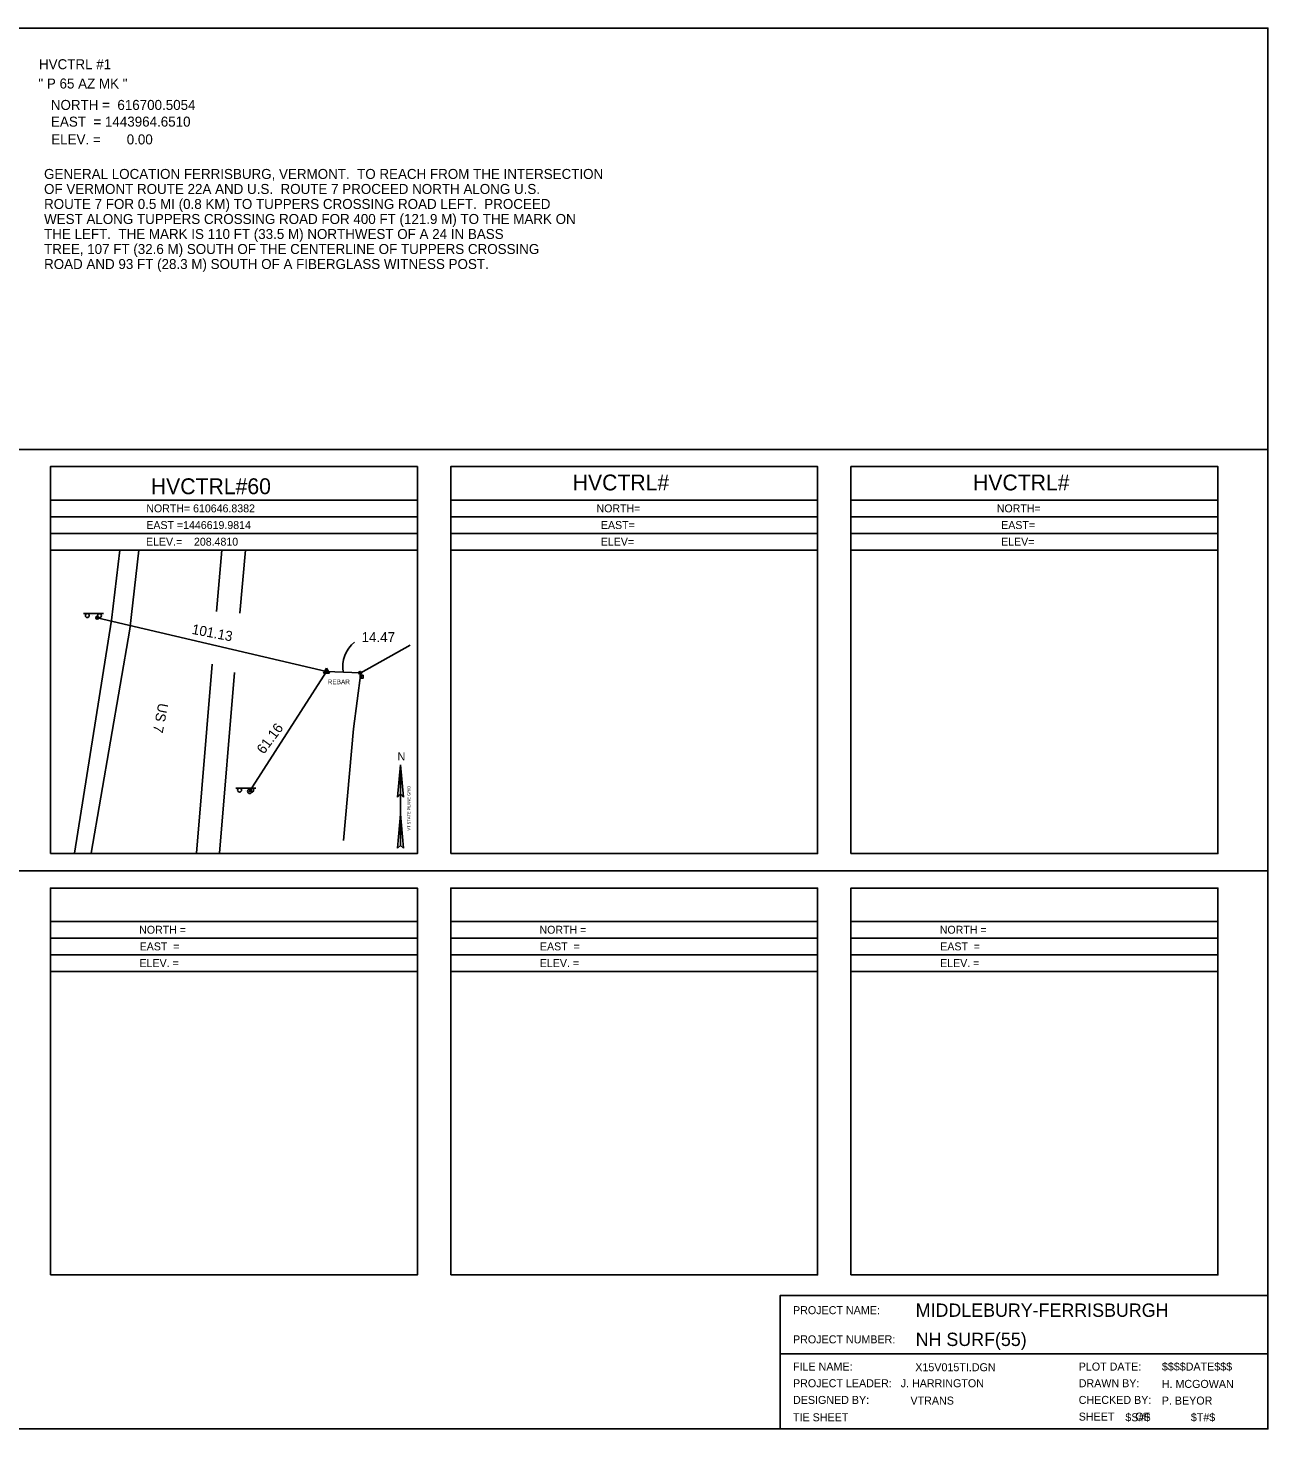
# Model space of a CAD drawing. Extents: x 1514039 to 1514679, y 870735 to 871155.
# Drawn here: x 1514306.9 to 1514678.6, y 870735.2 to 871155.2 of the extents above; entities that cross this region are included whole.
import ezdxf

# ---------------------------------------------------------------- set-up
doc = ezdxf.new("R2010")
doc.units = 0
for name, color, linetype in [('C_A', 7, 'Continuous'), ('CBP', 7, 'Continuous'), ('CPSM', 7, 'Continuous'), ('Default', 7, 'Continuous'), ('Level 18', 7, 'Continuous'), ('LFNC', 7, 'Continuous'), ('NBL1', 7, 'Continuous'), ('NBL2', 7, 'Continuous'), ('NNA_P', 7, 'Continuous'), ('PET', 7, 'Continuous'), ('PSP', 7, 'Continuous'), ('SSGN', 7, 'Continuous')]:
    doc.layers.add(name, color=color, linetype=linetype)

msp = doc.modelspace()

# ---------------------------------------------------------------- linework, layer by layer
at = {"layer": 'CBP'}
for centre, radius in [((1514327.61, 870978.41), 0.437), ((1514327.61, 870978.41), 0.0583), ((1514406.42, 870961.91), 0.437), ((1514406.42, 870961.91), 0.0583), ((1514373.29, 870926.35), 0.625), ((1514373.29, 870926.35), 0.0833)]:
    msp.add_circle(centre, radius, dxfattribs=at)
at = {"layer": 'CPSM'}
for p, q in [((1514395.45, 870961.78), (1514396.33, 870963.29)), ((1514397.2, 870961.78), (1514396.33, 870963.29)), ((1514396.33, 870962.28), (1514396.33, 870963.29)), ((1514395.45, 870961.78), (1514396.33, 870962.28)), ((1514395.45, 870961.78), (1514397.2, 870961.78)), ((1514396.33, 870962.28), (1514396.33, 870962.28)), ((1514396.33, 870962.28), (1514397.2, 870961.78))]:
    msp.add_line(p, q, dxfattribs=at)
at = {"layer": 'Default'}
msp.add_line((1514396.33, 870962.28), (1514406.42, 870961.91), dxfattribs=at)
msp.add_lwpolyline([(1514327.61, 870978.41), (1514396.33, 870962.28), (1514373.29, 870926.35)], dxfattribs=at)
msp.add_arc((1514410.48, 870963.82), 9.27, 127.984, 190.758, dxfattribs=at)
at = {"layer": 'Level 18'}
msp.add_lwpolyline([(1514406.45, 870961.18), (1514407.33, 870961.18), (1514407.33, 870960.3), (1514406.45, 870960.3)], close=True, dxfattribs=at)
msp.add_circle((1514406.89, 870960.74), 0.0583, dxfattribs=at)
at = {"layer": 'LFNC'}
msp.add_lwpolyline([(1514401.46, 870911.63), (1514404.45, 870945.15), (1514406.59, 870961.91), (1514421.39, 870970.18)], dxfattribs=at)
at = {"layer": 'NBL1'}
msp.add_line((1514532.32, 870757.72), (1514678.57, 870757.72), dxfattribs=at)
msp.add_lwpolyline([(1514038.57, 870735.22), (1514678.57, 870735.22), (1514678.57, 871155.22), (1514038.57, 871155.22)], close=True, dxfattribs=at)
msp.add_lwpolyline([(1514678.57, 870775.22), (1514532.32, 870775.22), (1514532.32, 870735.22)], dxfattribs=at)
at = {"layer": 'NBL2'}
for p, q in [((1514038.57, 871028.89), (1514678.57, 871028.89)), ((1514423.57, 871013.72), (1514313.57, 871013.72)), ((1514543.57, 871013.72), (1514433.57, 871013.72)), ((1514663.57, 871013.72), (1514553.57, 871013.72)), ((1514423.57, 871008.72), (1514313.57, 871008.72)), ((1514543.57, 871008.72), (1514433.57, 871008.72)), ((1514663.57, 871008.72), (1514553.57, 871008.72)), ((1514423.57, 871003.72), (1514313.57, 871003.72)), ((1514543.57, 871003.72), (1514433.57, 871003.72)), ((1514663.57, 871003.72), (1514553.57, 871003.72)), ((1514423.57, 870998.72), (1514313.57, 870998.72)), ((1514543.57, 870998.72), (1514433.57, 870998.72)), ((1514663.57, 870998.72), (1514553.57, 870998.72)), ((1514038.57, 870902.55), (1514678.57, 870902.55)), ((1514423.57, 870887.39), (1514313.57, 870887.39)), ((1514543.57, 870887.39), (1514433.57, 870887.39)), ((1514663.57, 870887.39), (1514553.57, 870887.39)), ((1514423.57, 870882.39), (1514313.57, 870882.39)), ((1514543.57, 870882.39), (1514433.57, 870882.39)), ((1514663.57, 870882.39), (1514553.57, 870882.39)), ((1514423.57, 870877.39), (1514313.57, 870877.39)), ((1514543.57, 870877.39), (1514433.57, 870877.39)), ((1514663.57, 870877.39), (1514553.57, 870877.39)), ((1514423.57, 870872.39), (1514313.57, 870872.39)), ((1514543.57, 870872.39), (1514433.57, 870872.39)), ((1514663.57, 870872.39), (1514553.57, 870872.39))]:
    msp.add_line(p, q, dxfattribs=at)
for points in [[(1514313.57, 870907.72), (1514423.57, 870907.72), (1514423.57, 871023.72), (1514313.57, 871023.72)], [(1514433.57, 870907.72), (1514543.57, 870907.72), (1514543.57, 871023.72), (1514433.57, 871023.72)], [(1514553.57, 870907.72), (1514663.57, 870907.72), (1514663.57, 871023.72), (1514553.57, 871023.72)], [(1514313.57, 870781.39), (1514423.57, 870781.39), (1514423.57, 870897.39), (1514313.57, 870897.39)], [(1514433.57, 870781.39), (1514543.57, 870781.39), (1514543.57, 870897.39), (1514433.57, 870897.39)], [(1514553.57, 870781.39), (1514663.57, 870781.39), (1514663.57, 870897.39), (1514553.57, 870897.39)]]:
    msp.add_lwpolyline(points, close=True, dxfattribs=at)
at = {"layer": 'NNA_P'}
for p, q in [((1514417.67, 870924.63), (1514418.54, 870934.37)), ((1514418.54, 870910.15), (1514418.54, 870934.37)), ((1514419.4, 870924.63), (1514418.54, 870934.37)), ((1514417.67, 870924.63), (1514418.54, 870925.59)), ((1514419.41, 870924.63), (1514418.54, 870925.59)), ((1514418.54, 870919.56), (1514417.64, 870909.36)), ((1514418.54, 870919.56), (1514419.44, 870909.36)), ((1514418.54, 870910.15), (1514417.64, 870909.36)), ((1514418.54, 870910.15), (1514419.44, 870909.36))]:
    msp.add_line(p, q, dxfattribs=at)
at = {"layer": 'PET'}
for points in [[(1514340.11, 870998.72), (1514337.42, 870975), (1514325.77, 870907.83)], [(1514364.96, 870998.72), (1514363.4, 870980.3)], [(1514362.07, 870964.48), (1514357.38, 870907.86)]]:
    msp.add_lwpolyline(points, dxfattribs=at)
at = {"layer": 'PSP'}
for points in [[(1514334.34, 870998.72), (1514331.87, 870977.69), (1514320.8, 870907.85)], [(1514372.05, 870998.72), (1514370.34, 870979.78)], [(1514368.78, 870961.99), (1514364.24, 870907.88)]]:
    msp.add_lwpolyline(points, dxfattribs=at)
at = {"layer": 'SSGN'}
for p, q in [((1514323.47, 870979.65), (1514329.48, 870979.65)), ((1514326.28, 870979.02), (1514326.28, 870979.02)), ((1514369.12, 870927.34), (1514375.14, 870927.34)), ((1514371.94, 870926.71), (1514371.94, 870926.71))]:
    msp.add_line(p, q, dxfattribs=at)
for centre in [(1514324.63, 870979.07), (1514328.28, 870979.02), (1514370.29, 870926.76), (1514373.94, 870926.71)]:
    msp.add_circle(centre, 0.583, dxfattribs=at)

# ---------------------------------------------------------------- texts
at = {"layer": 'C_A'}
msp.add_text('REBAR', height=1.4, dxfattribs=at).set_placement((1514396.7, 870958.5))
at = {"layer": 'Default'}
for s, p in [(' GENERAL LOCATION FERRISBURG, VERMONT.  TO REACH FROM THE INTERSECTION   ', (1514310.56, 871109.97)), (' OF VERMONT ROUTE 22A AND U.S.  ROUTE 7 PROCEED NORTH ALONG U.S.         ', (1514310.56, 871105.47)), (' ROUTE 7 FOR 0.5 MI (0.8 KM) TO TUPPERS CROSSING ROAD LEFT.  PROCEED     ', (1514310.56, 871100.97)), (' WEST ALONG TUPPERS CROSSING ROAD FOR 400 FT (121.9 M) TO THE MARK ON    ', (1514310.56, 871096.47)), (' THE LEFT.  THE MARK IS 110 FT (33.5 M) NORTHWEST OF A 24 IN BASS        ', (1514310.56, 871091.97)), (' TREE, 107 FT (32.6 M) SOUTH OF THE CENTERLINE OF TUPPERS CROSSING       ', (1514310.56, 871087.47)), (' ROAD AND 93 FT (28.3 M) SOUTH OF A FIBERGLASS WITNESS POST.  ', (1514310.56, 871082.97)), ('14.47', (1514406.85, 870971.11))]:
    msp.add_text(s, height=3, dxfattribs=at).set_placement(p)
for s, rotation, p in [('101.13', 349.1784, (1514355.81, 870973.61)), ('US 7', 259.0059, (1514345.97, 870953.01)), ('61.16', 53.243, (1514377.56, 870937.33))]:
    msp.add_text(s, height=3, rotation=rotation, dxfattribs=at).set_placement(p)
at = {"layer": 'NBL1'}
for s, height, p in [('PROJECT NAME:', 2.4, (1514536.19, 870769.64)), ('MIDDLEBURY-FERRISBURGH', 4, (1514572.96, 870768.84)), ('PROJECT NUMBER:', 2.4, (1514536.19, 870760.89)), ('NH SURF(55)', 4, (1514572.96, 870760.09)), ('FILE NAME:', 2.4, (1514536.19, 870752.73)), ('X15V015TI.DGN                 ', 2.4, (1514572.84, 870752.53)), ('PLOT DATE:', 2.4, (1514621.84, 870752.73)), ('$$$$DATE$$$', 2.4, (1514646.77, 870752.73)), ('PROJECT LEADER:   J. HARRINGTON ', 2.4, (1514536.19, 870747.73)), ('DRAWN BY:', 2.4, (1514621.84, 870747.73)), ('H. MCGOWAN   ', 2.4, (1514646.74, 870747.53)), ('DESIGNED BY:', 2.4, (1514536.19, 870742.73)), (' VTRANS             ', 2.4, (1514570.51, 870742.53)), ('CHECKED BY:', 2.4, (1514621.84, 870742.73)), ('P. BEYOR', 2.4, (1514646.74, 870742.53)), ('TIE SHEET ', 2.4, (1514536.19, 870737.53)), ('SHEET       OF', 2.4, (1514621.84, 870737.73)), ('$S#$ ', 2.4, (1514635.82, 870737.53)), ('$T#$   ', 2.4, (1514655.44, 870737.53))]:
    msp.add_text(s, height=height, dxfattribs=at).set_placement(p)
at = {"layer": 'NBL2'}
for s, height, p in [('  HVCTRL #1', 3, (1514307.92, 871142.87)), ('  " P 65 AZ MK "', 3, (1514307.75, 871137.08)), ('NORTH =  616700.5054', 3, (1514313.7, 871130.66)), ('EAST  = 1443964.6510', 3, (1514313.76, 871125.66)), ('ELEV. =       0.00', 3, (1514313.82, 871120.33)), ('HVCTRL#', 4.75, (1514470.14, 871016.6)), ('HVCTRL#', 4.75, (1514590.14, 871016.6)), ('HVCTRL#60', 4.75, (1514343.67, 871015.47)), ('NORTH= 610646.8382', 2.375, (1514342.32, 871010.03)), ('NORTH=', 2.375, (1514477.28, 871010.03)), ('NORTH=', 2.375, (1514597.28, 871010.03)), ('EAST =1446619.9814', 2.375, (1514342.33, 871005.03)), ('EAST=', 2.375, (1514478.6, 871005.03)), ('EAST=', 2.375, (1514598.6, 871005.03)), ('ELEV.=    208.4810', 2.375, (1514342.22, 871000.03)), ('ELEV=', 2.375, (1514478.57, 871000.03)), ('ELEV=', 2.375, (1514598.57, 871000.03)), ('NORTH =             ', 2.375, (1514340.19, 870883.7)), ('NORTH =             ', 2.375, (1514460.19, 870883.7)), ('NORTH =             ', 2.375, (1514580.19, 870883.7)), ('EAST  =             ', 2.375, (1514340.33, 870878.7)), ('EAST  =             ', 2.375, (1514460.33, 870878.7)), ('EAST  =             ', 2.375, (1514580.33, 870878.7)), ('ELEV. =             ', 2.375, (1514340.3, 870873.7)), ('ELEV. =             ', 2.375, (1514460.3, 870873.7)), ('ELEV. =             ', 2.375, (1514580.3, 870873.7))]:
    msp.add_text(s, height=height, dxfattribs=at).set_placement(p)
at = {"layer": 'NNA_P'}
msp.add_text('N', height=2.47, dxfattribs=at).set_placement((1514417.59, 870935.64))
msp.add_text('VT STATE PLANE GRID', height=0.875, rotation=90.0204, dxfattribs=at).set_placement((1514421.48, 870914.61))

doc.saveas('drawing.dxf')
